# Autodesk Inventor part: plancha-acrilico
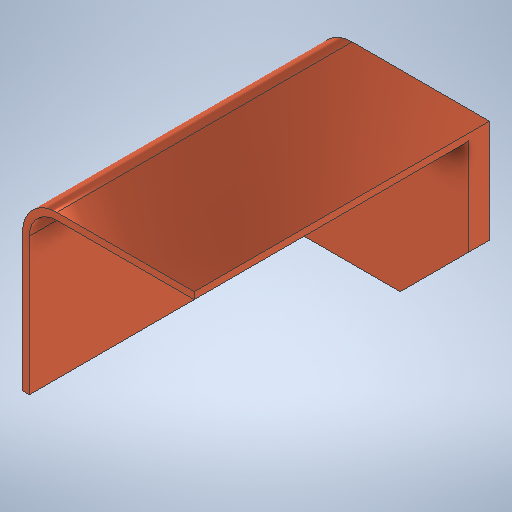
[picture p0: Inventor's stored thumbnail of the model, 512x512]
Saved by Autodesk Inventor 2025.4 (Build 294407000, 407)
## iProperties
Created: 2026-06
Part Number: plancha-acrilico
Material: Generic
Document SubType Name: Modeling
Designer: Marcio Valenzuela
Density: 1 g/cm^3
Appearance: Default
Author: Marcio Valenzuela
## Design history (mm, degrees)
sketch "Sketch1"
  geometry: L1 (0, 0)-(-1, 0); L2 (4, 4)-(4, 5); A1 r 4 centre (4, 0) between (4, 4) and (0, 0); A2 r 5 centre (4, 0) between (4, 5) and (-1, 0)
  constraints: 4 end point, 4 point on circle, 2 centre point, 1 concentric, 1 horizontal, 1 vertical
  dimensions: "d9" = 1 distance of L1.start L1.end; "d10" = 1 distance of L2.start L2.end
extrude "Extrusion1" new body sketch "Sketch1" distance "d2" = 40; taper "d3" = 0 deg
sketch "Sketch2"
  geometry: L1 (0, -1)-(0, 0) reference; L2 (40, -5)-(40, -1) reference; L3 (0, 0)-(40, 0); L4 (40, 0)-(40, -1); L5 (40, -1)-(0, -1); L6 (0, -1)-(0, 0); 1 further point
  constraints: 8 end point, 2 parallel, 1 horizontal, 1 perpendicular
extrude "Extrusion2" join sketch "Sketch2" distance "d11" = 20; taper "d12" = 0 deg
sketch "Sketch3"
  geometry: L1 (-1, 0)-(-1, 40) reference; L2 (-1, 40)-(0, 40); L3 (0, 40)-(0, 0); L4 (0, 0)-(-1, 0); L5 (-1, 0)-(-1, 40); 1 further point
  constraints: 8 end point, 2 parallel, 1 horizontal, 1 perpendicular
extrude "Extrusion3" join sketch "Sketch3" distance "d13" = 20; taper "d14" = 0 deg
sketch "Sketch4"
  geometry: L1 (-24, 5)-(-24, -20); L2 (0, -20)-(1, -20) reference; L3 (-24, -20)-(1, -20); L4 (1, -20)-(1, 0); L5 (-24, 5)-(-4, 5); A1 r 5 centre (-4, 0) between (1, 0) and (-4, 5); 1 further point
  constraints: 8 end point, 2 point on circle, 1 centre point, 1 horizontal, 1 perpendicular, 1 vertical
extrude "Extrusion4" join sketch "Sketch4" distance "d15" = 3; taper "d16" = 0 deg
chamfer "Chamfer1" distance "d17" = 10; stored, may be unused: second distance "d18" = 2, angle "d19" = 45 deg
body "Solid1"
